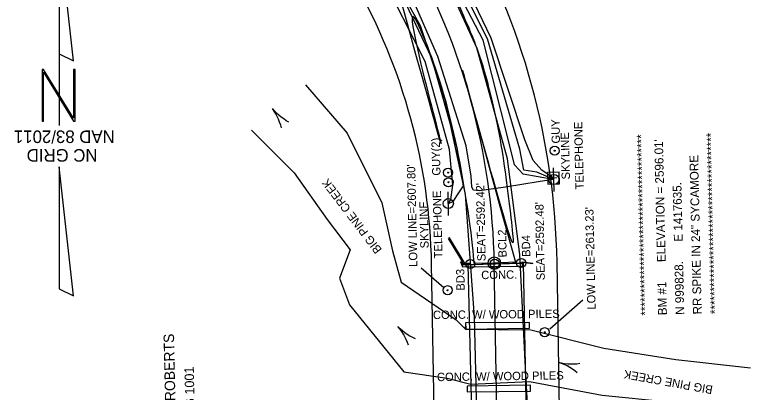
# Model space of a CAD drawing. Extents: x 1417249 to 1417944, y 999313 to 1000321.
# Drawn here: x 1417333.9 to 1417687.9, y 999902.2 to 1000082.8 of the extents above; entities that cross this region are included whole.
import ezdxf

# ---------------------------------------------------------------- set-up
doc = ezdxf.new("R2010")
doc.units = 0
for name, color, linetype in [('CTL North Arrow NAD 83 2001 CELL', 7, 'Continuous'), ('CTL Sheet Text', 7, 'Continuous'), ('Exist Horizontal Alignment', 7, 'Continuous'), ('Exist Horizontal Alignment Point', 7, 'Continuous'), ('Exist Hydro Stream Flow Arrow CELL', 7, 'Continuous'), ('Exist Hydro Stream or Body of Water', 7, 'Continuous'), ('Exist Hydro Stream or Body of Water Text', 7, 'Continuous'), ('Exist Other Culture Anchor (Guy Wire) CELL', 7, 'Continuous'), ('Exist Other Culture Anchor (Guy Wire) Text', 7, 'Continuous'), ('Exist Other Culture Located Object CELL', 7, 'Continuous'), ('Exist Other Culture Located Object Text', 7, 'Continuous'), ('Exist Property Deed Book Text', 7, 'Continuous'), ('Exist Property Owner Text', 7, 'Continuous'), ('Exist Right of Way Line', 7, 'Continuous'), ('Exist Roads EOP', 7, 'Continuous'), ('Exist Roads EOP Other', 7, 'Continuous'), ('Exist Roads EOP Other Text', 7, 'Continuous'), ('Exist Structure Major Bridge Seat Top Elevation', 7, 'Continuous'), ('Exist Structure Major Bridge WW', 7, 'Continuous'), ('Exist Structure Major Deck Tunnel Box Culvert', 7, 'Continuous'), ('Exist Utilities Other Located Object CELL', 7, 'Continuous'), ('Exist Utilities Other Located Object Leader', 7, 'Continuous'), ('Exist Utilities Other Located Object Text', 7, 'Continuous'), ('Exist Utilities Telephone Pedestal CELL', 7, 'Continuous'), ('Exist Utilities Telephone Pole CELL', 7, 'Continuous'), ('Exist Utilities Telephone Pole Text', 7, 'Continuous'), ('Exist Utilities Telephone UG Cable SUE', 7, 'Continuous'), ('Exist Utilities Telephone UG FO SUE', 7, 'Continuous'), ('Exist Vegetation Woods Line', 7, 'Continuous')]:
    doc.layers.add(name, color=color, linetype=linetype)

# ---------------------------------------------------------------- blocks, each defined once
blk = doc.blocks.new('EXIST OTHER CULTURE LOCATED OBJECT')
at = {"layer": 'Exist Other Culture Located Object CELL'}
for radius in [0.0436, 0.0048]:
    blk.add_circle((0, 0), radius, dxfattribs=at)

msp = doc.modelspace()

# ---------------------------------------------------------------- linework, layer by layer
at = {"layer": 'CTL North Arrow NAD 83 2001 CELL'}
msp.add_line((1417355.3, 1000035.23), (1417355.3, 1000035.23), dxfattribs=at)
for points in [[(1417355.15, 1000122.52), (1417355.15, 1000064.2), (1417362.03, 1000060.76)], [(1417346.93, 1000031.97), (1417347.62, 1000031.97), (1417347.62, 1000055.3), (1417362.03, 1000031.97), (1417362.72, 1000031.97), (1417362.72, 1000056.66), (1417362.03, 1000056.66), (1417362.03, 1000033.33), (1417347.62, 1000056.66), (1417346.93, 1000056.66)], [(1417355.15, 999951.68), (1417362.03, 999948.27), (1417355.15, 1000010.01)]]:
    msp.add_lwpolyline(points, close=True, dxfattribs=at)
msp.add_lwpolyline([(1417355.15, 1000064.2), (1417355.15, 1000029.9)], dxfattribs=at)
at = {"layer": 'Exist Horizontal Alignment'}
msp.add_line((1417565.14, 999851.97), (1417563.2, 999963.97), dxfattribs=at)
msp.add_arc((1417249.88, 999958.54), 313.36, 0.9914, 29.5879, dxfattribs=at)
at = {"layer": 'Exist Horizontal Alignment Point'}
msp.add_circle((1417563.2, 999963.97), 3, dxfattribs=at)
at = {"layer": 'Exist Hydro Stream Flow Arrow CELL'}
for p, q in [((1417460.15, 1000033.99), (1417460.15, 1000033.99)), ((1417520.46, 999929.93), (1417520.46, 999929.93)), ((1417598.7, 999915.09), (1417598.7, 999915.09))]:
    msp.add_line(p, q, dxfattribs=at)
for points in [[(1417465.02, 1000031.45), (1417463.73, 1000032.13), (1417462.49, 1000032.97), (1417461.27, 1000033.82), (1417460.16, 1000034.74), (1417459.07, 1000035.75), (1417458.03, 1000036.82), (1417457.07, 1000037.93)], [(1417461.41, 1000028.64), (1417461.07, 1000030.06), (1417460.55, 1000031.47), (1417460.03, 1000032.85), (1417459.41, 1000034.16), (1417458.7, 1000035.46), (1417457.91, 1000036.73), (1417457.07, 1000037.93)], [(1417525.51, 999927.74), (1417524.17, 999928.33), (1417522.87, 999929.08), (1417521.6, 999929.84), (1417520.42, 999930.68), (1417519.27, 999931.61), (1417518.15, 999932.61), (1417517.12, 999933.65)], [(1417522.11, 999924.68), (1417521.66, 999926.08), (1417521.05, 999927.45), (1417520.43, 999928.79), (1417519.72, 999930.05), (1417518.91, 999931.29), (1417518.04, 999932.51), (1417517.12, 999933.65)], [(1417604.14, 999915.9), (1417602.69, 999915.69), (1417601.19, 999915.64), (1417599.72, 999915.62), (1417598.27, 999915.71), (1417596.8, 999915.88), (1417595.33, 999916.14), (1417593.9, 999916.47)], [(1417602.88, 999911.5), (1417601.76, 999912.45), (1417600.52, 999913.29), (1417599.28, 999914.1), (1417598.01, 999914.79), (1417596.67, 999915.43), (1417595.28, 999915.99), (1417593.9, 999916.47)]]:
    msp.add_lwpolyline(points, dxfattribs=at)
at = {"layer": 'Exist Hydro Stream or Body of Water'}
for points in [[(1417472.95, 1000049.31), (1417492.82, 1000026.21), (1417509.43, 999992.85), (1417514.59, 999969.92), (1417518.65, 999954.82), (1417544.96, 999936.82), (1417549.34, 999932.32)], [(1417447.05, 1000027.54), (1417467.42, 1000007.21), (1417483.33, 999984.8), (1417494.25, 999970.36), (1417489.18, 999956.86)], [(1417489.18, 999956.86), (1417493.92, 999944.08), (1417519.87, 999911.97), (1417540.7, 999908.94), (1417551.94, 999906.04), (1417580.06, 999907.41), (1417614.71, 999900.78), (1417646.54, 999897.67), (1417687.93, 999890.16)], [(1417549.28, 999933.6), (1417549.34, 999932.32), (1417580.6, 999932.05), (1417615.62, 999923.36), (1417649.92, 999917.81), (1417685.77, 999913.92)]]:
    msp.add_lwpolyline(points, dxfattribs=at)
at = {"layer": 'Exist Other Culture Anchor (Guy Wire) CELL'}
for centre, radius in [((1417592.05, 1000017.77), 2.18), ((1417592.05, 1000017.77), 0.24), ((1417541.06, 1000007.28), 2.18), ((1417541.06, 1000007.28), 0.24), ((1417541.29, 1000002.68), 2.18), ((1417541.29, 1000002.68), 0.24)]:
    msp.add_circle(centre, radius, dxfattribs=at)
at = {"layer": 'Exist Right of Way Line'}
for p, q in [((1417595.19, 999849.65), (1417593.19, 999964.5)), ((1417535.15, 999851.38), (1417533.2, 999963.46))]:
    msp.add_line(p, q, dxfattribs=at)
for radius, end in [(343.36, 29.6632), (283.36, 29.5011)]:
    msp.add_arc((1417249.88, 999958.54), radius, 0.9939, end, dxfattribs=at)
at = {"layer": 'Exist Roads EOP'}
msp.add_lwpolyline([(1417573.26, 999964.44), (1417563.2, 999963.97), (1417553.54, 999963.77)], dxfattribs=at)
for points in [[(1417531.04, 1000117.83), (1417540.79, 1000099.65), (1417553, 1000072.65), (1417559.04, 1000055.14), (1417567.28, 1000020.01), (1417572.5, 999973.57), (1417573.26, 999964.44), (1417531.04, 1000117.83), (1417573.26, 999964.44)], [(1417553.54, 999963.77), (1417553.21, 999972.02), (1417546.68, 1000019.77), (1417533.34, 1000065.65), (1417513.34, 1000108.38), (1417553.54, 999963.77), (1417513.34, 1000108.38)]]:
    msp.add_open_spline(points, degree=3, dxfattribs=at)
at = {"layer": 'Exist Roads EOP Other'}
for p, q in [((1417546.98, 999964.55), (1417547.4, 999964.68)), ((1417576.56, 999963.98), (1417576.57, 999962.61)), ((1417550.26, 999902.34), (1417580.56, 999902.75))]:
    msp.add_line(p, q, dxfattribs=at)
for points in [[(1417546.98, 999964.55), (1417548.05, 999962.15), (1417561.53, 999962.37), (1417576.57, 999962.61)], [(1417576.56, 999963.98), (1417548.48, 999963.09), (1417547.4, 999964.68)], [(1417580.07, 999935.64), (1417549.47, 999935.37), (1417549.64, 999932.43), (1417580.01, 999932.83), (1417580.07, 999935.64)], [(1417580.56, 999902.75), (1417580.43, 999905.57), (1417550.25, 999905.18), (1417550.26, 999902.34)]]:
    msp.add_lwpolyline(points, dxfattribs=at)
at = {"layer": 'Exist Structure Major Bridge WW'}
msp.add_line((1417551.17, 999963.48), (1417551.11, 999963.9), dxfattribs=at)
for points in [[(1417551.11, 999963.9), (1417549.23, 999963.64), (1417541.71, 999976.03), (1417541.34, 999975.8)], [(1417551.11, 999963.9), (1417551.17, 999963.48), (1417549.01, 999963.18), (1417541.34, 999975.8)], [(1417576.52, 999964.39), (1417581.65, 999963.84), (1417581.62, 999964.02)]]:
    msp.add_lwpolyline(points, dxfattribs=at)
at = {"layer": 'Exist Structure Major Deck Tunnel Box Culvert'}
msp.add_lwpolyline([(1417550.63, 999963.4), (1417576.91, 999963.98), (1417578.68, 999874.14), (1417552.94, 999873.67)], close=True, dxfattribs=at)
msp.add_lwpolyline([(1417576.52, 999964.39), (1417576.49, 999964.57), (1417581.62, 999964.02)], dxfattribs=at)
at = {"layer": 'Exist Utilities Other Located Object CELL'}
for centre, radius in [((1417540.84, 999951.03), 2.18), ((1417540.84, 999951.03), 0.24), ((1417587.32, 999930.93), 2.18), ((1417587.32, 999930.93), 0.24)]:
    msp.add_circle(centre, radius, dxfattribs=at)
at = {"layer": 'Exist Utilities Other Located Object Leader'}
for p, q in [((1417539.07, 999952.15), (1417528.26, 999961.56)), ((1417589.7, 999932.61), (1417605.51, 999946.35))]:
    msp.add_line(p, q, dxfattribs=at)
at = {"layer": 'Exist Utilities Telephone Pedestal CELL'}
msp.add_line((1417591.52, 1000004.53), (1417591.52, 1000004.53), dxfattribs=at)
msp.add_lwpolyline([(1417594.41, 1000001.87), (1417594.27, 1000007.47), (1417588.68, 1000007.33), (1417588.82, 1000001.74), (1417594.41, 1000001.87)], dxfattribs=at)
at = {"layer": 'Exist Utilities Telephone Pole CELL'}
for p, q in [((1417591.82, 999998.29), (1417591.55, 1000009.63)), ((1417591.69, 1000003.97), (1417591.69, 1000003.97)), ((1417541.32, 999986.79), (1417541.05, 999998.12)), ((1417541.19, 999992.46), (1417541.19, 999992.46))]:
    msp.add_line(p, q, dxfattribs=at)
for centre in [(1417591.69, 1000003.97), (1417541.19, 999992.46)]:
    msp.add_circle(centre, 2.41, dxfattribs=at)
at = {"layer": 'Exist Utilities Telephone UG Cable SUE'}
for points in [[(1417591.27, 1000004.02), (1417577.04, 1000006.49), (1417572.84, 1000011), (1417570.48, 1000020.78), (1417557.93, 1000070.63), (1417536.07, 1000112.66), (1417508.55, 1000158.95), (1417483.9, 1000201.78)], [(1417591.33, 1000004.18), (1417583.55, 1000007.5), (1417577.23, 1000008.42), (1417575.41, 1000018.49), (1417559.99, 1000071.32), (1417537.22, 1000116.55), (1417510.39, 1000158.95), (1417485.24, 1000203.68)], [(1417591.36, 1000004.18), (1417591.56, 1000004.65), (1417585.89, 1000008.5), (1417581.84, 1000013.16), (1417577.73, 1000023), (1417561.71, 1000071.55), (1417539.75, 1000117.56), (1417511.7, 1000159.81), (1417487.23, 1000203.68)], [(1417541.25, 999992.49), (1417543.61, 999993.57), (1417545.26, 999996.24), (1417548.53, 1000000.94), (1417545.27, 1000019.59), (1417533.33, 1000061.97), (1417513.29, 1000104.5), (1417486.07, 1000144.95), (1417462.11, 1000191.79)], [(1417541.25, 999992.49), (1417542.42, 999994.35), (1417543.32, 1000001.3), (1417541.7, 1000018.34), (1417530.16, 1000060.41), (1417508.92, 1000102.47), (1417483.42, 1000142.39), (1417456.99, 1000189.91)]]:
    msp.add_lwpolyline(points, dxfattribs=at)
at = {"layer": 'Exist Utilities Telephone UG FO SUE'}
msp.add_lwpolyline([(1417591.27, 1000004.02), (1417584.17, 1000002.91), (1417568.52, 1000000.25), (1417555.98, 999998.58), (1417553.24, 999998.95), (1417552.44, 1000000.34), (1417552.16, 1000005.66), (1417549.7, 1000020.15), (1417536.24, 1000062.84), (1417517.06, 1000106.71), (1417487.42, 1000144.84), (1417462.97, 1000192.37)], dxfattribs=at)
at = {"layer": 'Exist Vegetation Woods Line'}
for points in [[(1417580.46, 999870.2), (1417578.16, 999914.11), (1417575.47, 999968.19), (1417569.51, 1000013.81), (1417554.85, 1000066.95), (1417534.46, 1000111.85), (1417506.86, 1000156.7), (1417485.45, 1000196.25), (1417470.81, 1000240.08)], [(1417451.06, 1000235.71), (1417460.15, 1000197.18), (1417483.87, 1000152.84), (1417505.64, 1000117.31), (1417527.8, 1000077.64), (1417539.61, 1000042.27), (1417549.29, 999996.88), (1417553.54, 999938.26), (1417555.22, 999873.36)]]:
    msp.add_lwpolyline(points, dxfattribs=at)

# ---------------------------------------------------------------- block references
at = {"layer": 'Exist Other Culture Located Object CELL', "xscale": 50.00000000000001, "yscale": 50.00000000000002, "rotation": -11.833767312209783}
for p in [(1417551.7, 999963.53), (1417563.39, 999963.76), (1417576.04, 999964.04)]:
    msp.add_blockref('EXIST OTHER CULTURE LOCATED OBJECT', p, dxfattribs=at)

# ---------------------------------------------------------------- texts
at = {"layer": 'CTL North Arrow NAD 83 2001 CELL'}
for s, p in [('NAD 83/2011', (1417381.69, 1000027.45)), ('NC GRID', (1417373.47, 1000018.54))]:
    msp.add_text(s, height=6, rotation=180, dxfattribs=at).set_placement(p)
at = {"layer": 'CTL Sheet Text'}
for s, p in [('****************************************', (1417637.38, 999938.93)), ('****************************************', (1417670.71, 999939.67)), ("BM #1      ELEVATION = 2596.01'", (1417645.71, 999939.12)), ('RR SPIKE IN 24" SYCAMORE', (1417662.37, 999939.49)), ('N 999828.      E 1417635.', (1417654.04, 999939.3))]:
    msp.add_text(s, height=4.1667, rotation=91.2799, dxfattribs=at).set_placement(p)
at = {"layer": 'Exist Hydro Stream or Body of Water Text'}
for rotation, p in [(127.0896, (1417509.64, 999970.43)), (169.7146, (1417667.89, 999905.21))]:
    msp.add_text('BIG PINE CREEK', height=4, rotation=rotation, dxfattribs=at).set_placement(p)
at = {"layer": 'Exist Other Culture Anchor (Guy Wire) Text'}
for s, p in [('GUY', (1417594.63, 1000021.26)), ('GUY(2)', (1417537.49, 1000005.89))]:
    msp.add_text(s, height=4, rotation=91.2799, dxfattribs=at).set_placement(p)
at = {"layer": 'Exist Other Culture Located Object Text'}
for s, p in [('BCL2', (1417569.11, 999966.74)), ('BD4', (1417580.43, 999967.01)), ('BD3', (1417549.05, 999950.84))]:
    msp.add_text(s, height=4, rotation=91.0252, dxfattribs=at).set_placement(p)
at = {"layer": 'Exist Property Deed Book Text'}
msp.add_text('DB 327 PG 1001', height=4.5, rotation=91.2799, dxfattribs=at).set_placement((1417420.5, 999869.05))
at = {"layer": 'Exist Property Owner Text'}
msp.add_text('LINDA MARIE ROBERTS', height=5, rotation=91.2799, dxfattribs=at).set_placement((1417411.73, 999853.42))
at = {"layer": 'Exist Roads EOP Other Text'}
for s, rotation, p in [('CONC.', 0.9216, (1417556.96, 999956.3)), ('CONC. W/ WOOD PILES', 0.5149, (1417533.86, 999937.23)), ('CONC. W/ WOOD PILES', 0.7772, (1417535.79, 999907.5))]:
    msp.add_text(s, height=4, rotation=rotation, dxfattribs=at).set_placement(p)
at = {"layer": 'Exist Structure Major Bridge Seat Top Elevation'}
for s, p in [("SEAT=2592.42'", (1417559.05, 999964.9)), ("SEAT=2592.48'", (1417587.34, 999955.8))]:
    msp.add_text(s, height=4, rotation=90.9888, dxfattribs=at).set_placement(p)
at = {"layer": 'Exist Utilities Other Located Object Text'}
for s, p in [("LOW LINE=2607.80'", (1417526.45, 999962.25)), ("LOW LINE=2613.23'", (1417611.64, 999941.8))]:
    msp.add_text(s, height=4, rotation=91.2799, dxfattribs=at).set_placement(p)
at = {"layer": 'Exist Utilities Telephone Pedestal CELL'}
msp.add_text('T', height=3.42, rotation=91.3853, dxfattribs=at).set_placement((1417593.26, 1000003.44))
at = {"layer": 'Exist Utilities Telephone Pole Text'}
for s, p in [('TELEPHONE', (1417605.99, 999999.3)), ('SKYLINE', (1417599.38, 1000004.07)), ('TELEPHONE', (1417538.44, 999966.32)), ('SKYLINE', (1417531.83, 999971.09))]:
    msp.add_text(s, height=4, rotation=91.2799, dxfattribs=at).set_placement(p)

doc.saveas('drawing.dxf')
